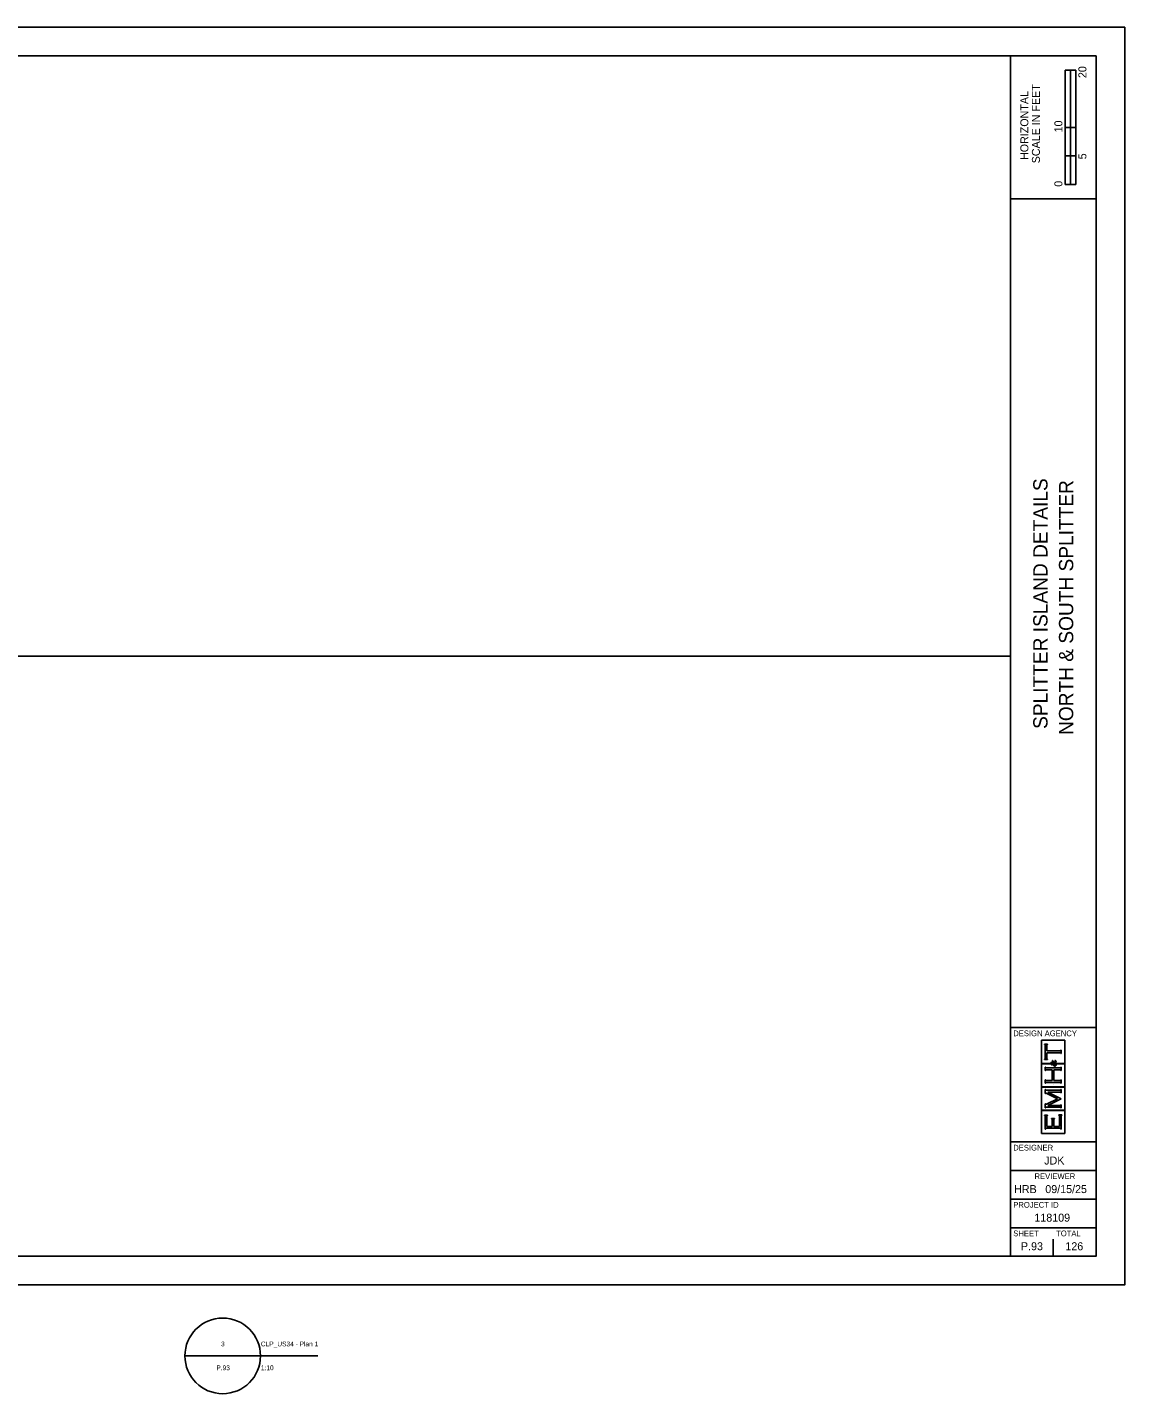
# Model space of a CAD drawing. Extents: x -4.4 to 34, y -1.9 to 22.
# Drawn here: x 14.8 to 34, y -1.9 to 22 of the extents above; entities that cross this region are included whole.
import ezdxf

# ---------------------------------------------------------------- set-up
doc = ezdxf.new("R2010")
doc.units = 0
for name, color, linetype in [('SH_Border', 7, 'Continuous'), ('SH_Cut_Line', 7, 'Continuous'), ('SH_Data', 7, 'Continuous'), ('SH_Named_Boundary', 7, 'Continuous'), ('SH_Text', 7, 'Continuous')]:
    doc.layers.add(name, color=color, linetype=linetype)

msp = doc.modelspace()

# ---------------------------------------------------------------- linework, layer by layer
at = {"layer": 'SH_Border'}
for p, q in [((32, 0.5), (32, 21.5)), ((32, 19), (33.5, 19)), ((32, 4.5), (33.5, 4.5)), ((32, 2.5), (33.5, 2.5)), ((32, 2), (33.5, 2)), ((32, 1.5), (33.5, 1.5)), ((32, 1), (33.5, 1))]:
    msp.add_line(p, q, dxfattribs=at)
msp.add_lwpolyline([(1.5, 21.5), (33.5, 21.5), (33.5, 0.5), (1.5, 0.5)], close=True, dxfattribs=at)
at = {"layer": 'SH_Cut_Line'}
msp.add_lwpolyline([(0, 0), (34, 0), (34, 22), (0, 22)], close=True, dxfattribs=at)
at = {"layer": 'SH_Data'}
for p, q in [((32.957, 19.25), (32.957, 21.25)), ((33.144, 21.25), (32.957, 21.25)), ((32.957, 20.25), (32.957, 21.25)), ((32.957, 21.25), (33.05, 21.25)), ((33.05, 21.25), (33.051, 21.25)), ((33.051, 21.25), (33.051, 20.25)), ((33.144, 21.25), (33.144, 19.25)), ((33.051, 20.25), (32.957, 20.25)), ((33.143, 20.25), (33.05, 20.25)), ((33.05, 20.25), (33.05, 19.75)), ((33.143, 19.75), (33.143, 20.25)), ((33.05, 19.75), (32.957, 19.75)), ((32.957, 19.75), (32.957, 19.25)), ((33.05, 19.25), (33.05, 19.75)), ((33.05, 19.75), (33.143, 19.75)), ((33.144, 19.25), (32.957, 19.25)), ((32.957, 19.25), (33.05, 19.25)), ((32.952, 4.279), (32.547, 4.279)), ((32.547, 4.279), (32.547, 3.875)), ((32.598, 4.204), (32.598, 4.211)), ((32.598, 4.211), (32.65, 4.211)), ((32.603, 4.203), (32.598, 4.204)), ((32.606, 4.201), (32.603, 4.203)), ((32.608, 4.199), (32.606, 4.201)), ((32.61, 4.196), (32.608, 4.199)), ((32.611, 4.192), (32.61, 4.196)), ((32.611, 4.187), (32.611, 4.192)), ((32.611, 3.968), (32.611, 4.187)), ((32.638, 4.196), (32.637, 4.192)), ((32.637, 4.192), (32.637, 4.187)), ((32.637, 4.187), (32.637, 4.093)), ((32.637, 4.093), (32.864, 4.093)), ((32.64, 4.199), (32.638, 4.196)), ((32.642, 4.201), (32.64, 4.199)), ((32.645, 4.203), (32.642, 4.201)), ((32.65, 4.204), (32.645, 4.203)), ((32.65, 4.211), (32.65, 4.204)), ((32.864, 4.093), (32.869, 4.093)), ((32.869, 4.093), (32.873, 4.094)), ((32.873, 4.094), (32.876, 4.096)), ((32.876, 4.096), (32.878, 4.097)), ((32.878, 4.097), (32.88, 4.101)), ((32.88, 4.101), (32.881, 4.106)), ((32.881, 4.106), (32.888, 4.106)), ((32.888, 4.106), (32.888, 4.048)), ((32.952, 3.875), (32.952, 4.279)), ((32.547, 3.875), (32.696, 3.875)), ((32.696, 3.869), (32.547, 3.869)), ((32.547, 3.869), (32.547, 3.465)), ((32.598, 3.95), (32.603, 3.951)), ((32.598, 3.944), (32.598, 3.95)), ((32.65, 3.944), (32.598, 3.944)), ((32.603, 3.951), (32.606, 3.953)), ((32.606, 3.953), (32.608, 3.955)), ((32.608, 3.955), (32.61, 3.958)), ((32.61, 3.958), (32.611, 3.962)), ((32.611, 3.962), (32.611, 3.968)), ((32.864, 4.061), (32.637, 4.061)), ((32.637, 4.061), (32.637, 3.968)), ((32.637, 3.968), (32.637, 3.962)), ((32.637, 3.962), (32.638, 3.958)), ((32.638, 3.958), (32.64, 3.955)), ((32.64, 3.955), (32.642, 3.953)), ((32.642, 3.953), (32.645, 3.951)), ((32.645, 3.951), (32.65, 3.95)), ((32.65, 3.95), (32.65, 3.944)), ((32.696, 3.875), (32.696, 3.869)), ((32.703, 3.879), (32.705, 3.883)), ((32.703, 3.873), (32.703, 3.879)), ((32.703, 3.868), (32.703, 3.873)), ((32.705, 3.863), (32.703, 3.868)), ((32.705, 3.883), (32.708, 3.887)), ((32.708, 3.858), (32.705, 3.863)), ((32.708, 3.887), (32.711, 3.89)), ((32.709, 3.879), (32.708, 3.876)), ((32.708, 3.876), (32.708, 3.873)), ((32.708, 3.873), (32.708, 3.869)), ((32.708, 3.869), (32.71, 3.866)), ((32.712, 3.853), (32.708, 3.858)), ((32.712, 3.881), (32.709, 3.879)), ((32.71, 3.866), (32.712, 3.864)), ((32.711, 3.89), (32.715, 3.892)), ((32.714, 3.883), (32.712, 3.881)), ((32.712, 3.864), (32.715, 3.862)), ((32.718, 3.85), (32.712, 3.853)), ((32.716, 3.884), (32.714, 3.883)), ((32.715, 3.892), (32.72, 3.892)), ((32.715, 3.862), (32.718, 3.861)), ((32.72, 3.884), (32.716, 3.884)), ((32.718, 3.861), (32.721, 3.861)), ((32.726, 3.85), (32.718, 3.85)), ((32.72, 3.892), (32.725, 3.892)), ((32.724, 3.884), (32.72, 3.884)), ((32.721, 3.861), (32.723, 3.861)), ((32.723, 3.861), (32.725, 3.862)), ((32.728, 3.882), (32.724, 3.884)), ((32.725, 3.892), (32.729, 3.89)), ((32.725, 3.862), (32.728, 3.862)), ((32.729, 3.85), (32.726, 3.85)), ((32.731, 3.88), (32.728, 3.882)), ((32.728, 3.862), (32.731, 3.863)), ((32.729, 3.89), (32.732, 3.887)), ((32.731, 3.85), (32.729, 3.85)), ((32.734, 3.877), (32.731, 3.88)), ((32.731, 3.863), (32.735, 3.865)), ((32.734, 3.851), (32.731, 3.85)), ((32.732, 3.887), (32.736, 3.883)), ((32.737, 3.872), (32.734, 3.877)), ((32.737, 3.852), (32.734, 3.851)), ((32.735, 3.865), (32.74, 3.867)), ((32.736, 3.883), (32.74, 3.878)), ((32.74, 3.867), (32.737, 3.872)), ((32.741, 3.853), (32.737, 3.852)), ((32.738, 3.893), (32.738, 3.922)), ((32.738, 3.922), (32.741, 3.922)), ((32.741, 3.893), (32.738, 3.893)), ((32.74, 3.878), (32.744, 3.869)), ((32.741, 3.922), (32.741, 3.918)), ((32.741, 3.918), (32.742, 3.915)), ((32.742, 3.896), (32.741, 3.895)), ((32.741, 3.895), (32.741, 3.893)), ((32.746, 3.855), (32.741, 3.853)), ((32.742, 3.915), (32.743, 3.913)), ((32.743, 3.897), (32.742, 3.896)), ((32.743, 3.913), (32.745, 3.911)), ((32.745, 3.899), (32.743, 3.897)), ((32.744, 3.869), (32.754, 3.875)), ((32.745, 3.911), (32.749, 3.908)), ((32.746, 3.899), (32.745, 3.899)), ((32.748, 3.899), (32.746, 3.899)), ((32.752, 3.844), (32.746, 3.855)), ((32.755, 3.899), (32.748, 3.899)), ((32.749, 3.908), (32.756, 3.904)), ((32.756, 3.86), (32.751, 3.857)), ((32.751, 3.857), (32.754, 3.852)), ((32.757, 3.837), (32.752, 3.844)), ((32.754, 3.875), (32.764, 3.881)), ((32.754, 3.852), (32.757, 3.848)), ((32.763, 3.895), (32.755, 3.899)), ((32.756, 3.904), (32.763, 3.9)), ((32.761, 3.863), (32.756, 3.86)), ((32.757, 3.848), (32.761, 3.845)), ((32.763, 3.833), (32.757, 3.837)), ((32.764, 3.865), (32.761, 3.863)), ((32.761, 3.845), (32.765, 3.843)), ((32.763, 3.9), (32.77, 3.896)), ((32.772, 3.887), (32.763, 3.895)), ((32.768, 3.829), (32.763, 3.833)), ((32.764, 3.881), (32.772, 3.887)), ((32.768, 3.867), (32.764, 3.865)), ((32.765, 3.843), (32.769, 3.841)), ((32.774, 3.872), (32.768, 3.867)), ((32.774, 3.827), (32.768, 3.829)), ((32.769, 3.841), (32.773, 3.841)), ((32.77, 3.896), (32.776, 3.891)), ((32.773, 3.841), (32.778, 3.841)), ((32.782, 3.878), (32.774, 3.872)), ((32.779, 3.827), (32.774, 3.827)), ((32.776, 3.891), (32.781, 3.895)), ((32.778, 3.841), (32.782, 3.843)), ((32.779, 3.923), (32.781, 3.926)), ((32.782, 3.922), (32.779, 3.923)), ((32.785, 3.827), (32.779, 3.827)), ((32.781, 3.926), (32.787, 3.924)), ((32.781, 3.895), (32.784, 3.898)), ((32.785, 3.921), (32.782, 3.922)), ((32.786, 3.873), (32.782, 3.878)), ((32.782, 3.843), (32.786, 3.846)), ((32.784, 3.898), (32.786, 3.901)), ((32.786, 3.919), (32.785, 3.921)), ((32.79, 3.829), (32.785, 3.827)), ((32.788, 3.917), (32.786, 3.919)), ((32.786, 3.901), (32.788, 3.904)), ((32.791, 3.886), (32.786, 3.881)), ((32.786, 3.881), (32.791, 3.876)), ((32.788, 3.869), (32.786, 3.873)), ((32.786, 3.846), (32.789, 3.849)), ((32.787, 3.924), (32.792, 3.921)), ((32.789, 3.914), (32.788, 3.917)), ((32.788, 3.904), (32.789, 3.908)), ((32.79, 3.867), (32.788, 3.869)), ((32.789, 3.911), (32.789, 3.914)), ((32.789, 3.908), (32.789, 3.911)), ((32.789, 3.849), (32.791, 3.853)), ((32.791, 3.864), (32.79, 3.867)), ((32.793, 3.834), (32.79, 3.829)), ((32.794, 3.89), (32.791, 3.886)), ((32.791, 3.876), (32.795, 3.87)), ((32.791, 3.861), (32.791, 3.864)), ((32.791, 3.859), (32.791, 3.861)), ((32.791, 3.853), (32.791, 3.859)), ((32.792, 3.921), (32.795, 3.918)), ((32.797, 3.838), (32.793, 3.834)), ((32.796, 3.894), (32.794, 3.89)), ((32.795, 3.918), (32.798, 3.914)), ((32.795, 3.87), (32.797, 3.866)), ((32.798, 3.897), (32.796, 3.894)), ((32.797, 3.866), (32.798, 3.861)), ((32.799, 3.844), (32.797, 3.838)), ((32.798, 3.914), (32.799, 3.91)), ((32.799, 3.901), (32.798, 3.897)), ((32.798, 3.861), (32.799, 3.857)), ((32.799, 3.91), (32.799, 3.905)), ((32.799, 3.905), (32.799, 3.901)), ((32.803, 3.869), (32.799, 3.875)), ((32.799, 3.875), (32.952, 3.875)), ((32.799, 3.857), (32.799, 3.852)), ((32.799, 3.852), (32.799, 3.844)), ((32.952, 3.869), (32.803, 3.869)), ((32.87, 4.061), (32.864, 4.061)), ((32.874, 4.06), (32.87, 4.061)), ((32.876, 4.059), (32.874, 4.06)), ((32.878, 4.057), (32.876, 4.059)), ((32.88, 4.053), (32.878, 4.057)), ((32.881, 4.048), (32.88, 4.053)), ((32.888, 4.048), (32.881, 4.048)), ((32.952, 3.465), (32.952, 3.869)), ((32.611, 3.749), (32.611, 3.807)), ((32.611, 3.807), (32.617, 3.807)), ((32.617, 3.749), (32.611, 3.749)), ((32.617, 3.807), (32.619, 3.802)), ((32.618, 3.754), (32.617, 3.749)), ((32.62, 3.758), (32.618, 3.754)), ((32.619, 3.802), (32.62, 3.798)), ((32.62, 3.798), (32.623, 3.797)), ((32.623, 3.76), (32.62, 3.758)), ((32.623, 3.797), (32.625, 3.795)), ((32.625, 3.761), (32.623, 3.76)), ((32.625, 3.795), (32.629, 3.794)), ((32.629, 3.762), (32.625, 3.761)), ((32.629, 3.794), (32.635, 3.794)), ((32.635, 3.762), (32.629, 3.762)), ((32.635, 3.794), (32.864, 3.794)), ((32.732, 3.762), (32.635, 3.762)), ((32.732, 3.572), (32.732, 3.762)), ((32.864, 3.762), (32.759, 3.762)), ((32.759, 3.762), (32.759, 3.572)), ((32.864, 3.794), (32.869, 3.794)), ((32.87, 3.762), (32.864, 3.762)), ((32.869, 3.794), (32.873, 3.795)), ((32.874, 3.761), (32.87, 3.762)), ((32.873, 3.795), (32.876, 3.797)), ((32.876, 3.76), (32.874, 3.761)), ((32.876, 3.797), (32.878, 3.798)), ((32.878, 3.758), (32.876, 3.76)), ((32.878, 3.798), (32.88, 3.802)), ((32.88, 3.754), (32.878, 3.758)), ((32.88, 3.802), (32.881, 3.807)), ((32.881, 3.749), (32.88, 3.754)), ((32.881, 3.807), (32.888, 3.807)), ((32.888, 3.749), (32.881, 3.749)), ((32.888, 3.807), (32.888, 3.749)), ((32.547, 3.465), (32.952, 3.465)), ((32.952, 3.459), (32.547, 3.459)), ((32.547, 3.459), (32.547, 3.055)), ((32.611, 3.527), (32.611, 3.585)), ((32.611, 3.585), (32.617, 3.585)), ((32.617, 3.527), (32.611, 3.527)), ((32.611, 3.345), (32.611, 3.418)), ((32.611, 3.418), (32.617, 3.418)), ((32.617, 3.585), (32.619, 3.58)), ((32.618, 3.532), (32.617, 3.527)), ((32.617, 3.418), (32.619, 3.412)), ((32.62, 3.352), (32.617, 3.345)), ((32.62, 3.536), (32.618, 3.532)), ((32.619, 3.58), (32.62, 3.576)), ((32.619, 3.412), (32.62, 3.409)), ((32.62, 3.576), (32.623, 3.574)), ((32.623, 3.537), (32.62, 3.536)), ((32.62, 3.409), (32.623, 3.407)), ((32.622, 3.355), (32.62, 3.352)), ((32.626, 3.355), (32.622, 3.355)), ((32.623, 3.574), (32.625, 3.573)), ((32.625, 3.539), (32.623, 3.537)), ((32.623, 3.407), (32.625, 3.405)), ((32.625, 3.573), (32.629, 3.572)), ((32.629, 3.54), (32.625, 3.539)), ((32.625, 3.405), (32.629, 3.405)), ((32.629, 3.355), (32.626, 3.355)), ((32.629, 3.572), (32.635, 3.572)), ((32.635, 3.54), (32.629, 3.54)), ((32.629, 3.405), (32.635, 3.405)), ((32.633, 3.353), (32.629, 3.355)), ((32.64, 3.35), (32.633, 3.353)), ((32.635, 3.572), (32.732, 3.572)), ((32.864, 3.54), (32.635, 3.54)), ((32.635, 3.405), (32.864, 3.405)), ((32.825, 3.257), (32.64, 3.35)), ((32.864, 3.373), (32.654, 3.373)), ((32.654, 3.373), (32.888, 3.255)), ((32.75, 3.5), (32.75, 3.5)), ((32.759, 3.572), (32.864, 3.572)), ((32.864, 3.572), (32.87, 3.572)), ((32.87, 3.54), (32.864, 3.54)), ((32.864, 3.405), (32.869, 3.405)), ((32.87, 3.373), (32.864, 3.373)), ((32.869, 3.405), (32.873, 3.405)), ((32.87, 3.572), (32.874, 3.573)), ((32.874, 3.539), (32.87, 3.54)), ((32.874, 3.372), (32.87, 3.373)), ((32.873, 3.405), (32.876, 3.407)), ((32.874, 3.573), (32.876, 3.574)), ((32.876, 3.538), (32.874, 3.539)), ((32.876, 3.37), (32.874, 3.372)), ((32.876, 3.574), (32.878, 3.576)), ((32.878, 3.536), (32.876, 3.538)), ((32.876, 3.407), (32.878, 3.409)), ((32.878, 3.369), (32.876, 3.37)), ((32.878, 3.576), (32.88, 3.58)), ((32.88, 3.532), (32.878, 3.536)), ((32.878, 3.409), (32.88, 3.412)), ((32.88, 3.365), (32.878, 3.369)), ((32.88, 3.58), (32.881, 3.585)), ((32.881, 3.527), (32.88, 3.532)), ((32.88, 3.412), (32.881, 3.418)), ((32.881, 3.36), (32.88, 3.365)), ((32.881, 3.585), (32.888, 3.585)), ((32.888, 3.527), (32.881, 3.527)), ((32.881, 3.418), (32.888, 3.418)), ((32.888, 3.36), (32.881, 3.36)), ((32.888, 3.585), (32.888, 3.527)), ((32.888, 3.418), (32.888, 3.36)), ((32.952, 3.055), (32.952, 3.459)), ((32.617, 3.345), (32.611, 3.345)), ((32.611, 3.096), (32.611, 3.168)), ((32.611, 3.168), (32.617, 3.168)), ((32.617, 3.168), (32.62, 3.162)), ((32.62, 3.162), (32.622, 3.158)), ((32.622, 3.158), (32.626, 3.158)), ((32.625, 3.109), (32.623, 3.107)), ((32.629, 3.109), (32.625, 3.109)), ((32.626, 3.158), (32.627, 3.158)), ((32.627, 3.158), (32.633, 3.161)), ((32.635, 3.109), (32.629, 3.109)), ((32.633, 3.161), (32.641, 3.165)), ((32.864, 3.109), (32.635, 3.109)), ((32.641, 3.165), (32.825, 3.257)), ((32.888, 3.255), (32.654, 3.138)), ((32.654, 3.138), (32.864, 3.138)), ((32.864, 3.138), (32.869, 3.138)), ((32.87, 3.109), (32.864, 3.109)), ((32.869, 3.138), (32.873, 3.139)), ((32.874, 3.109), (32.87, 3.109)), ((32.873, 3.139), (32.876, 3.141)), ((32.876, 3.107), (32.874, 3.109)), ((32.876, 3.141), (32.878, 3.143)), ((32.878, 3.143), (32.88, 3.146)), ((32.88, 3.146), (32.881, 3.151)), ((32.881, 3.151), (32.888, 3.151)), ((32.888, 3.151), (32.888, 3.096)), ((32.547, 3.055), (32.952, 3.055)), ((32.952, 3.049), (32.547, 3.049)), ((32.547, 3.049), (32.547, 2.645)), ((32.598, 2.962), (32.598, 2.969)), ((32.598, 2.969), (32.65, 2.969)), ((32.603, 2.961), (32.598, 2.962)), ((32.606, 2.959), (32.603, 2.961)), ((32.608, 2.957), (32.606, 2.959)), ((32.61, 2.955), (32.608, 2.957)), ((32.611, 2.951), (32.61, 2.955)), ((32.617, 3.096), (32.611, 3.096)), ((32.611, 2.945), (32.611, 2.951)), ((32.611, 2.725), (32.611, 2.945)), ((32.618, 3.102), (32.617, 3.096)), ((32.62, 3.105), (32.618, 3.102)), ((32.623, 3.107), (32.62, 3.105)), ((32.64, 2.957), (32.638, 2.955)), ((32.638, 2.955), (32.638, 2.951)), ((32.638, 2.951), (32.638, 2.945)), ((32.638, 2.945), (32.638, 2.77)), ((32.642, 2.959), (32.64, 2.957)), ((32.645, 2.961), (32.642, 2.959)), ((32.65, 2.962), (32.645, 2.961)), ((32.65, 2.969), (32.65, 2.962)), ((32.719, 2.902), (32.719, 2.908)), ((32.719, 2.908), (32.772, 2.908)), ((32.724, 2.901), (32.719, 2.902)), ((32.728, 2.899), (32.724, 2.901)), ((32.729, 2.896), (32.728, 2.899)), ((32.731, 2.894), (32.729, 2.896)), ((32.732, 2.89), (32.731, 2.894)), ((32.732, 2.884), (32.732, 2.89)), ((32.732, 2.77), (32.732, 2.884)), ((32.76, 2.894), (32.759, 2.89)), ((32.759, 2.89), (32.759, 2.884)), ((32.759, 2.884), (32.759, 2.77)), ((32.761, 2.896), (32.76, 2.894)), ((32.763, 2.899), (32.761, 2.896)), ((32.767, 2.901), (32.763, 2.899)), ((32.772, 2.902), (32.767, 2.901)), ((32.772, 2.908), (32.772, 2.902)), ((32.848, 2.965), (32.848, 2.972)), ((32.848, 2.972), (32.901, 2.972)), ((32.853, 2.964), (32.848, 2.965)), ((32.857, 2.962), (32.853, 2.964)), ((32.859, 2.96), (32.857, 2.962)), ((32.86, 2.958), (32.859, 2.96)), ((32.861, 2.953), (32.86, 2.958)), ((32.861, 2.948), (32.861, 2.953)), ((32.861, 2.77), (32.861, 2.948)), ((32.878, 3.105), (32.876, 3.107)), ((32.88, 3.102), (32.878, 3.105)), ((32.881, 3.096), (32.88, 3.102)), ((32.888, 3.096), (32.881, 3.096)), ((32.889, 2.957), (32.888, 2.953)), ((32.888, 2.953), (32.888, 2.948)), ((32.888, 2.948), (32.888, 2.725)), ((32.891, 2.96), (32.889, 2.957)), ((32.892, 2.962), (32.891, 2.96)), ((32.896, 2.964), (32.892, 2.962)), ((32.901, 2.965), (32.896, 2.964)), ((32.901, 2.972), (32.901, 2.965)), ((32.952, 2.645), (32.952, 3.049)), ((32.547, 2.645), (32.952, 2.645)), ((32.617, 2.725), (32.611, 2.725)), ((32.619, 2.73), (32.617, 2.725)), ((32.62, 2.734), (32.619, 2.73)), ((32.623, 2.735), (32.62, 2.734)), ((32.625, 2.737), (32.623, 2.735)), ((32.629, 2.738), (32.625, 2.737)), ((32.635, 2.738), (32.629, 2.738)), ((32.864, 2.738), (32.635, 2.738)), ((32.638, 2.77), (32.732, 2.77)), ((32.759, 2.77), (32.861, 2.77)), ((32.87, 2.738), (32.864, 2.738)), ((32.874, 2.737), (32.87, 2.738)), ((32.876, 2.735), (32.874, 2.737)), ((32.878, 2.734), (32.876, 2.735)), ((32.88, 2.73), (32.878, 2.734)), ((32.881, 2.725), (32.88, 2.73)), ((32.888, 2.725), (32.881, 2.725)), ((32.75, 0.5), (32.75, 0.8)), ((32.375, 0.675), (32.375, 0.675))]:
    msp.add_line(p, q, dxfattribs=at)
at = {"layer": 'SH_Named_Boundary'}
for p, q in [((17.556, -1.243), (18.879, -1.243)), ((18.223, -1.243), (19.88, -1.243))]:
    msp.add_line(p, q, dxfattribs=at)
msp.add_circle((18.217, -1.243), 0.661, dxfattribs=at)
at = {"layer": 'SH_Text'}
msp.add_line((1.5, 11), (32, 11), dxfattribs=at)

# ---------------------------------------------------------------- texts
at = {"layer": 'SH_Data'}
for s, height, p in [('20', 0.14, (33.33, 21.112)), ('HORIZONTAL', 0.14, (32.315, 19.679)), ('SCALE IN FEET', 0.14, (32.517, 19.621)), ('10', 0.14, (32.91, 20.162)), ('5', 0.14, (33.33, 19.691)), ('0', 0.14, (32.91, 19.211)), ('SPLITTER ISLAND DETAILS ', 0.25, (32.65, 9.726)), ('NORTH & SOUTH SPLITTER ', 0.25, (33.1, 9.62))]:
    msp.add_text(s, height=height, rotation=90, dxfattribs=at).set_placement(p)
for s, height, p in [('DESIGN AGENCY', 0.1, (32.05, 4.35)), ('DESIGNER', 0.1, (32.05, 2.35)), ('JDK', 0.14, (32.592, 2.105)), ('REVIEWER', 0.1, (32.422, 1.85)), ('HRB', 0.14, (32.066, 1.605)), ('09/15/25', 0.14, (32.611, 1.605)), ('PROJECT ID', 0.1, (32.05, 1.35)), ('118109', 0.14, (32.42, 1.105)), ('SHEET', 0.1, (32.05, 0.85)), ('P.93', 0.14, (32.185, 0.605)), ('TOTAL', 0.1, (32.8, 0.85)), ('126', 0.14, (32.962, 0.605))]:
    msp.add_text(s, height=height, dxfattribs=at).set_placement(p)
at = {"layer": 'SH_Named_Boundary'}
for s, height, p in [('3', 0.0833, (18.188, -1.076)), ('CLP_US34 - Plan 1', 0.08333, (18.885, -1.076)), ('P.93', 0.0833, (18.106, -1.493)), ('1:10', 0.0833, (18.885, -1.493))]:
    msp.add_text(s, height=height, dxfattribs=at).set_placement(p)

doc.saveas('drawing.dxf')
